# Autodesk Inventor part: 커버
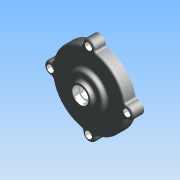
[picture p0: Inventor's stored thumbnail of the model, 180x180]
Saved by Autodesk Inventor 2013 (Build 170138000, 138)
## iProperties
Created: 2012-05
Part Number: 커버
Document SubType Name: 모델링
Designer: SeoGD™
Material: 알루미늄 6061
Mass: 196.659 g
Surface Area: 278.607 cm^2
Volume: 72.5678 cm^3
Density: 2.71 g/cm^3
변환 표준: STEP AP214IS
파일 이름: C:\Users\SeoGD\Desktop\?쒗뿕\而ㅻ쾭-1.stp
전처리기: Build: 253, Release: 2010 SP1 - Date: Wed 07/29/2009
전송 단위: 밀리미터
불확실성: 0.01
Author: SeoGD™
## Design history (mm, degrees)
sketch "스케치1"
  geometry: L1 (0, 0)-(0, 26); L2 (50, 0)-(50, 15); L3 (50, 15)-(25, 15); L4 (25, 15)-(25, 21); L5 (25, 21)-(15, 21); L6 (15, 21)-(13.66, 26); L7 (13.66, 26)-(10, 26); L8 (50, 0)-(45, 0); L9 (45, 0)-(45, 10); L10 (45, 10)-(14.5, 10); L11 (14.5, 10)-(13.266, 3); L12 (13.266, 3)-(11, 3); L13 (11, 3)-(11, 16); L14 (11, 16)-(7.5, 16); L15 (7.5, 16)-(7.5, 19); L16 (7.5, 19)-(10, 19); L17 (10, 19)-(10, 26)
  constraints: 34 end point, 10 parallel, 2 perpendicular, 2 point on line, 1 vertical
  dimensions: "d11" = 100 diameter of L2 L1; "d12" = 22 diameter of L13 L1; "d13" = 90 diameter of L9 L1; "d14" = 15 distance between parallel lines of L3 L8; "d15" = 10 distance between parallel lines of L8 L10; "d16" = 29 diameter of L10.end L1; "d17" = 100 deg angle of L11 L10; "d18" = 7 distance between parallel lines of L12 L10; "d19" = 13 distance between parallel lines of L14 L12; "d20" = 3 distance between parallel lines of L16 L14; "d21" = 15 diameter of L15 L1; "d22" = 20 diameter of L17 L1; "d23" = 30 diameter of L5.end L1; "d24" = 6 distance between parallel lines of L5 L3; "d25" = 50 diameter of L4 L1; "d26" = 105 deg angle of L5 L6; "d50" = 26 distance of L1.start L1.end
revolve "회전1" sketch "스케치1" stored, may be unused: angle "d27" = 90 deg
sketch "스케치2" dims "d29" = 104
  geometry: A1 r 8.5 centre (0, 52) between (8.074, 49.344) and (-8.074, 49.344); A2 r 50 centre (0, 0) between (-8.074, 49.344) and (8.074, 49.344) reference; 2 further points
  constraints: 4 point on circle, 2 vertical alignment, 1 centre point, 1 coincident, 2 other
  dimensions: "d28" = 17 diameter of A1
extrude "돌출1" join sketch "스케치2" stored distance "d30" = 10; taper "d31" = 0 deg
fillet "모깎기3" dims "d32" = 3
fillet "모깎기4" dims "d45" = 3, "d46" = 0.2
chamfer "모따기1" distance "d47" = 1; stored, may be unused: second distance "d48" = 2, angle "d49" = 45 deg
hole "구멍2" diameter "d38" = 5.5; stored, may be unused: countersink angle "d42" = 90 deg, drill point angle "d44" = 118 deg; dims "d36" = 10, "d37" = 10, "d39" = 6, "d40" = 9.5, "d41" = 5.4, "d43" = 8
node "솔리드1"
node "솔리드 본체"
node "곡면 본체"
pattern_circular "원형 패턴1" dims angle "d34" = 360 deg
pattern_circular "원형 패턴2" dims angle "d52" = 360 deg
node "솔리드2"
